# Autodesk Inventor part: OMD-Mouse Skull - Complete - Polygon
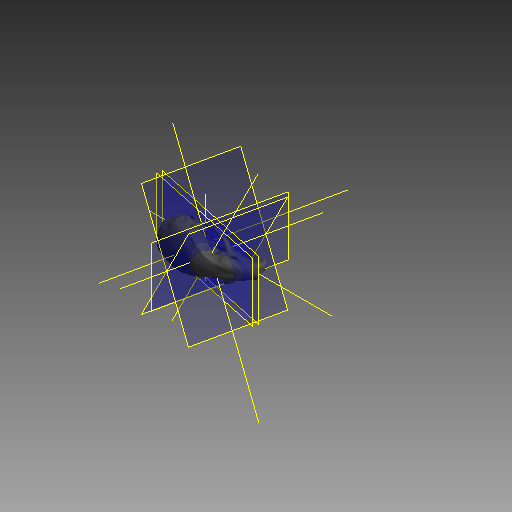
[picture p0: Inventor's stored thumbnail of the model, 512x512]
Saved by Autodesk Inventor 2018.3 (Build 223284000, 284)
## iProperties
Created: 2013-10
Part Number: OMD-Mouse Skull - Complete - Polygon
Material: Generic
Document SubType Name: Modeling
Designer: JORDANJ
Appearance: Default
Translation Standard: STEP AP203
FileName: __GRANITE__1
PreProcessor: PRO/ENGINEER BY PARAMETRIC TECHNOLOGY CORPORATION, 2012230
PostProcessor: Build: 219, Release: 2012 SP2 - Date: Fri 04/27/2012
Sent Units: inch
Uncertainty: 7.104820940729999e-05
Author: JORDANJ
Revision Number: 0
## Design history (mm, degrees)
workplane "Work Plane2 MOUSE"
node "__GRANITE__11"
sketch "Sketch1"
  geometry: 5 further points
  constraints: 4 other
  node "Projected Loop1"
sketch "Sketch3 - MOUSE L POSITIONS"
  geometry: L1 (0, 2.8)-(0, -2.8) reference; L2 (-16.896, 0)-(2.816, 0) reference; L3 (-3.099, 1.5)-(-3.099, -1.5); 5 further points
  constraints: 3 point on line, 2 end point, 1 coincident, 1 midpoint, 1 vertical
  dimensions: "d4" = 3 distance of L3.start L3.end; "d5" = 1.5 distance of point (-4.599, 0) point (-3.099, 0); "d12" = 1.5 distance from line of point (-1.599, 0) L3
workplane "Work Plane3 RAT"
sketch "Sketch4"
  geometry: L1 (-16.896, 0)-(2.816, 0) reference; L2 (0, 2.8)-(0, -2.8) reference; L3 (-5.08, 2)-(-5.08, -2); L4 (-5.08, 0)-(-14.08, 0); 1 further point
  constraints: 4 end point, 1 midpoint, 1 point on line, 1 symmetric about line, 1 vertical
  dimensions: "d8" = 4 distance of L3.start L3.end; "d9" = 9 distance of L4.start L4.end; "d11" = 5.08 distance from line of point (0, 0) L3
workaxis "Work Axis1"
workaxis "Work Axis2"
workaxis "Work Axis3"
workaxis "Work Axis4"
workpoint "Work Point1"
workaxis "Work Axis5 Central Axis BREGMA"
workplane "Work Plane5"
  workplane "Work Plane4"
workaxis "Work Axis6 LAMBDA"
sketch "Sketch5"
  geometry: L1 (0, 11.178)-(0, -4.837) reference; C1 r 6.858 at (0, 1.237); 2 further points
  constraints: 1 centre point, 1 coincident, 1 point on line
  dimensions: "d14" = 13.716 diameter of C1
workaxis "Work Axis7"
workplane "Work Plane6"
workplane "Work Plane7"
workplane "Work Plane8"
workaxis "Work Axis8"
workpoint "Work Point2"
node "Rotate around  L-R Work Plane9"
workplane "Work Plane10"
node "Rotate around F-B Work Plane12"
workplane "Work Plane13"
workplane "Work Plane14"
workaxis "Work Axis10"
workplane "Work Plane16"
workaxis "Work Axis11"
workplane "Work Plane17"
workplane "Work Plane19"
workaxis "Work Axis13"
  workplane "Work Plane18"
workaxis "Work Axis14"
node "__GRANITE__1"
node "Base1"
other parameters: "d3" = 8.255, "d7" = 8.89, "d13" = -4, "d15" = 8 deg, "d16" = 90 deg, "d17" = 55 deg, "d18" = 70 deg, "d19" = 90 deg, "d21" = -3.556, "d22" = 30 deg, "d23" = -30 deg, "d24" = -1.27
